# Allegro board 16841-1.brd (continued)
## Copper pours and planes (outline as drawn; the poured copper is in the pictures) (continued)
DCBATOUT on TOP: 184.81,2.63 184.55,2.88 184.55,5.68 179.98,10.25 179.98,16.72 178.84,17.87 175.28,17.87 171.41,21.74 171.41,28.6 167.28,32.73 167.28,38.44 167.41,38.57 167.41,51.27 167.66,51.52 168.42,51.52 168.68,51.78 168.68,52.28 168.42,52.54 167.28,52.54 167.28,54.95 169.82,54.95 170.58,54.19 171.22,54.19 172.49,52.92 172.49,51.27 172.55,51.21 172.55,50.57 172.11,50.13 172.11,46.44 174.77,43.78 178.46,43.78 181.5,46.82 181.5,47.97 182.01,48.47 185.31,48.47 185.57,48.22 185.57,44.66 185.31,44.41 180.49,44.41 178.46,42.38 178.46,33.11 180.74,30.82 185.57,30.82 186.33,31.58 186.33,32.47 186.58,32.73 190.14,32.73 191.28,31.58 191.28,26.5 190.39,25.61 176.55,25.61 175.15,24.22 175.15,21.8 176.42,20.53 184.17,20.53 187.47,17.23 187.47,10.12 188.49,9.1 188.49,2.88 188.23,2.63 ; 6 cut-outs
DCBATOUT on BOTTOM: 123.97,1.61 123.72,1.87 123.72,4.15 124.73,4.15 124.73,6.56 125.88,6.56 126,6.44 126,1.87 125.75,1.61
DCBATOUT on BOTTOM: 52.47,100.04 52.34,100.16 52.34,100.93 52.98,101.56 52.98,103.21 53.11,103.34 54.5,103.34 54.76,103.08 54.76,100.93 53.87,100.04
DCBATOUT on BOTTOM: 181.76,44.66 181.5,44.92 181.5,47.84 182.14,48.47 185.44,48.47 185.57,48.35 185.57,44.79 185.44,44.66
DCBATOUT on BOTTOM: 180.74,24.98 180.61,25.11 180.61,29.04 180.87,29.3 182.01,29.3 182.39,29.68 182.39,32.85 182.52,32.98 184.68,32.98 185.19,33.49 193.06,33.49 193.19,33.36 193.19,32.47 193.06,32.35 191.79,32.35 191.41,31.96 191.16,31.96 190.77,31.58 190.77,27.77 191.41,27.14 191.41,25.87 191.16,25.61 182.27,25.61 182.01,25.36 182.01,25.11 181.88,24.98 ; 3 cut-outs
DCBATOUT on BOTTOM: 140.74,106.01 140.63,106.11 140.63,111.39 140.43,111.59 138.83,111.59 138.58,111.85 138.58,114.13 138.7,114.26 143.78,114.26 144.17,113.88 144.17,106.13 144.04,106.01 ; 3 cut-outs
DCBATOUT on BOTTOM: 167.66,33.36 167.53,33.49 167.53,36.54 167.91,36.92 169.69,36.92 169.82,37.04 169.82,41.74 172.23,41.74 172.36,41.62 172.36,34.76 170.96,33.36
DCBATOUT on BOTTOM: 189.38,72.22 189.25,72.35 189.25,73.44 189.24,73.46 189.25,73.47 189.25,73.76 189.76,74.27 190.96,74.27 191.59,74.89 192.68,74.89 193.44,75.65 198.67,75.65 198.85,75.48 198.85,74.21 199.12,73.94 199.12,73.46 199.03,73.37 198.65,73.37 198.39,73.62 198.39,74.51 198.14,74.76 197,74.76 196.36,74.13 194.58,74.13 194.33,73.87 194.33,72.48 194.08,72.22 ; 3 cut-outs
DCBATOUT on BOTTOM: 169.82,47.59 169.82,51.4 169.69,51.52 168.8,51.52 168.68,51.65 168.68,52.16 168.3,52.54 167.28,52.54 167.28,55.84 167.41,55.97 168.93,55.97 169.31,55.59 169.31,54.44 169.82,53.94 169.82,51.78 170.07,51.52 170.07,51.14 170.58,50.63 171.85,50.63 172.11,50.38 172.11,47.97 171.85,47.71 171.6,47.71 171.47,47.59 ; 2 cut-outs
DCBATOUT on BOTTOM: 187.35,62.32 187.35,63.46 186.71,64.1 185.57,64.1 185.19,64.48 185.19,67.14 185.31,67.27 187.98,67.27 188.36,66.89 188.36,66 190.52,63.84 190.52,62.44 190.39,62.32
DCBATOUT on BOTTOM: 118.89,100.54 118.77,100.67 118.77,101.69 118.64,101.81 86.51,101.81 86,102.32 84.88,102.32 84.73,102.17 81.66,102.17 81.55,102.27 81.55,103.21 81.68,103.34 120.67,103.34 121.56,104.23 121.56,105.75 122.32,106.51 123.59,106.51 123.97,106.89 123.97,113.88 124.35,114.26 129.43,114.26 129.56,114.13 129.56,111.72 129.43,111.59 127.78,111.59 127.5,111.31 127.5,105.73 126.51,104.74 126.51,101.31 125.88,100.67 124.23,100.67 124.1,100.8 122.7,100.8 122.45,100.54 ; 3 cut-outs
DCBATOUT on L3: 185.31,4.91 188.36,4.91 188.62,4.66 188.62,1.61 188.23,1.23 144.57,1.23 144.22,1.59 144.22,2.58 144.77,3.14 154.2,3.14 154.96,3.9 175.03,3.9 175.53,3.39 183.79,3.39
DCBATOUT on L3: 121.31,102.96 121.31,103.21 121.05,103.47 120.16,103.47 120.04,103.34 82.19,103.34 81.94,103.08 81.94,99.96 83.13,98.77 87.8,98.77 88.39,99.35 89.35,99.35 89.38,99.33 117.67,99.33
DCBATOUT on L4: 81.94,102.7 82.19,102.45 115.72,102.45 116.35,101.81 121.05,101.81 121.81,102.58 121.81,103.08 121.56,103.34 82.06,103.34 81.94,103.21
DCBATOUT on L4: 175.28,4.28 175.79,3.77 184.55,3.77 185.06,4.28 188.49,4.28 188.74,4.02 188.74,1.61 188.36,1.23 126.39,1.23 126.32,1.29 126.26,1.23 124.23,1.23 123.85,1.61 123.85,5.68 123.86,5.69 123.86,6.91 126.08,9.13 132.79,9.13 135.94,5.98 139.8,5.98 140.28,5.5 141.4,5.5 142.44,4.46 161.79,4.46 162.45,3.8 162.45,3.01 162.71,2.75 163.34,2.75 163.47,2.88 163.47,4.02 163.49,4.05 163.49,4.51 163.77,4.79 171.9,4.79 172.41,4.28
DCBATOUT on L6: 124.23,105.62 123.97,105.88 123.97,113.88 124.23,114.13 127.53,114.13 129.43,116.04 142.01,116.04 144.17,113.88 144.17,106.13 144.04,106.01 140.61,106.01 140.48,106.13 140.48,112.61 139.97,113.12 129.81,113.12 127.66,110.96 127.66,105.88 127.4,105.62
DCBATOUT on L6: 53.61,103.34 84.48,103.34 84.6,103.21 84.6,101.31 83.84,100.54 54,100.54 53.36,101.18 53.36,103.08
DCBATOUT on L6: 182.96,59.21 182.96,62.25 183.66,62.95 183.66,68.48 184.61,69.43 184.61,71.4 187.09,73.87 191.41,73.87 192.55,75.02 195.6,75.02 195.85,74.76 195.85,73.11 190.01,67.27 190.01,62.57 189.25,61.81 189.25,60.16 187.73,58.63 187.73,55.59 187.79,55.52 187.79,50.44 185.69,48.35 185.69,44.41 184.55,43.27 180.36,43.27 178.2,41.11 178.2,33.49 179.98,31.71 183.54,31.71 184.68,30.57 188.11,30.57 189.63,29.04 191.03,29.04 191.41,28.66 191.41,27.77 191.03,27.39 173.88,27.39 167.91,33.36 167.91,44.28 167.98,44.35 167.98,55.4 170.07,57.49 170.07,61.17 168.55,62.7 168.55,68.16 169.31,68.92 169.31,69.56 168.93,69.94 166.01,69.94 165.12,70.83 164.74,70.83 164.49,71.08 164.49,72.22 164.61,72.35 172.11,72.35 175.53,68.92 175.53,63.97 174.14,62.57 174.14,59.02 176.04,57.11 180.87,57.11
DCBATOUT_CAMERA on TOP: 114.57,96.99 114.32,97.24 114.32,101.18 115.21,102.07 116.48,102.07 116.73,101.81 116.73,100.54 115.46,99.27 115.46,97.75 114.7,96.99 ; 4 cut-outs
DCBATOUT_CAMERA on BOTTOM: 114.22,96.02 114.19,96.05 114.19,98.03 114.4,98.23 115.21,98.23 115.29,98.16 115.29,96.15 115.16,96.02
DCBATOUT_LCD on TOP: 88.54,93.81 87.52,94.83 87.52,99.02 87.78,99.27 91.97,99.27 92.53,98.72 92.53,96.25 90.09,93.81 ; 3 cut-outs
DCBATOUT_LCD on BOTTOM: 90.11,95.96 89.93,96.14 89.93,96.84 89.92,96.84 89.92,97.72 89.91,97.73 89.91,97.98 90.11,98.18 92.04,98.18 92.58,97.65 92.58,97.22 92.43,97.07 92.07,97.07 92,97 92,96.01 91.95,95.96
EC_AGND on TOP: 146.71,2.25 146.58,2.37 146.58,4.41 146.83,4.66 149.37,4.66 149.5,4.53 149.5,3.77 149.75,3.52 150.26,3.52 150.26,2.37 150.13,2.25 148.74,2.25 148.67,2.31 148.61,2.25 ; 7 cut-outs
ECVBAT on TOP: 160.17,2.88 160.04,3.01 160.04,3.64 159.91,3.77 159.41,3.77 159.28,3.9 159.28,4.41 159.41,4.53 162.45,4.53 162.58,4.41 162.58,4.02 162.45,3.9 161.95,3.9 161.82,3.77 161.82,3.14 161.69,3.01 160.8,3.01 160.68,2.88 ; 1 cut-out
EDP_COMP on TOP: 125.88,63.08 125.75,63.21 125.75,64.48 126.39,65.11 128.04,65.11 128.16,64.98 128.16,64.1 128.04,63.97 126.77,63.97 126.51,63.71 126.51,63.21 126.39,63.08
EDRAM_OPIO_RCOMP on TOP: 126.24,71.79 126.16,71.86 126.16,72.34 125.93,72.57 125.5,72.57 125.4,72.67 125.4,73.13 125.47,73.21 125.93,73.21 126.29,72.85 126.64,72.85 126.77,72.98 127.02,72.98 127.1,72.9 127.1,72.6 126.69,72.19 126.69,71.91 126.57,71.79
FAN_VCC_1 on TOP: 202.59,68.54 202.33,68.79 202.33,69.05 203.98,70.7 203.98,74.26 204.36,74.64 206.27,74.64 206.52,74.38 206.52,72.22 206.4,72.1 205.63,72.1 205.13,71.59 205.13,70.7 202.97,68.54 ; 3 cut-outs
FBA_PLL_AVDD on L3: 162.33,90 168.04,90 168.17,89.88 168.17,85.56 168.8,84.92 168.8,84.42 168.68,84.29 167.91,84.29 167.66,84.54 167.66,88.73 167.15,89.24 163.47,89.24 162.07,87.84 156.99,87.84 156.48,88.35 150.9,88.35 150.52,88.73 150.52,89.24 150.64,89.37 157.63,89.37 158.39,88.61 161.31,88.61 162.2,89.5 162.2,89.88
GPU_PLL_VDD on L6: 163.98,76.54 163.98,76.03 162.96,75.02 162.96,70.57 163.6,69.94 165.12,69.94 165.25,70.06 165.25,70.32 164.99,70.57 164.61,70.57 164.23,70.95 164.23,74.51 164.99,75.27 164.99,76.16 164.49,76.67 164.1,76.67
GT_CORE on TOP: 123.21,59.4 122.83,59.78 122.83,62.44 122.96,62.57 122.96,63.46 123.08,63.59 124.35,63.59 124.99,64.22 125.37,64.22 125.62,63.97 125.62,63.46 125.37,63.21 124.99,63.21 124.73,62.95 124.73,62.7 125.12,62.32 125.37,62.32 125.62,62.06 125.62,60.41 125.37,60.16 124.73,60.16 124.61,60.03 124.61,59.65 124.35,59.4
GT_CORE on BOTTOM: 126,59.65 126,60.41 124.99,60.41 124.73,60.67 124.73,64.1 124.89,64.25 125.29,64.25 125.72,63.82 125.85,63.82 125.98,63.94 125.98,64.53 126.05,64.6 126.13,64.6 126.26,64.73 126.39,64.73 126.51,64.6 126.51,59.78 126.39,59.65
GT_CORE on L4: 131.21,65.49 130.07,65.49 129.18,64.6 129.18,62.83 128.8,62.44 126.39,62.44 126,62.83 126,63.97 125.5,64.48 124.86,64.48 124.48,64.1 124.48,59.96 124.63,59.8 125.14,59.8 125.47,59.47 125.47,59.02 125.72,58.76 128.04,58.76 129.56,60.29 129.56,60.41 130.45,61.3 131.34,61.3 131.47,61.43 131.47,62.7 130.96,63.21 130.96,64.6 131.34,64.98 131.34,65.37
GTX_CORE on TOP: 114.7,60.41 114.57,60.54 114.57,64.73 114.83,64.98 116.1,64.98 116.23,64.86 116.23,60.54 116.1,60.41
GTX_CORE on BOTTOM: 115.34,58.48 114.81,59.01 114.81,59.16 115.26,59.62 115.26,60.25 114.81,60.71 114.81,61.02 115.29,61.5 115.29,62.03 115.16,62.16 114.75,62.16 114.58,61.98 114.5,61.98 114.35,62.13 114.35,64.22 114.45,64.32 114.45,64.98 114.57,65.11 115.97,65.11 116.25,64.83 116.25,59.26 115.47,58.48
JGND on TOP: 17.55,89.5 17.04,90 17.04,91.02 16.02,92.04 15.9,92.04 15.9,92.92 15.39,93.43 15.39,96.73 15.64,96.99 18.56,96.99 18.69,96.86 18.69,94.7 19.32,94.07 19.32,89.88 18.94,89.5 ; 4 cut-outs
JGND on BOTTOM: 15.23,89.95 15.01,90.18 15.01,93.05 15.26,93.31 18.44,93.31 18.69,93.05 18.69,91.91 18.44,91.65 17.83,91.65 17.75,91.58 17.75,89.95
LCDVDD on BOTTOM: 100.73,91.91 100.48,92.16 100.48,93.69 100.73,93.94 102.13,93.94 103.02,94.83 103.09,94.83 103.63,95.36 104.39,95.36 104.72,95.69 104.72,96.89 104.77,96.94 106.47,96.94 106.5,96.91 106.5,92.47 105.94,91.91 ; 5 cut-outs
M_VREF_CA_DIMMA on TOP: 62.89,43.52 62.63,43.78 62.63,44.54 63.79,45.69 69.25,45.69 69.43,45.87 69.43,47.13 69.55,47.26 70.07,47.26 70.19,47.14 70.19,46 70.82,45.36 70.82,44.6 70.7,44.47 68.97,44.47 68.43,45.01 64.37,45.01 63.39,44.03 63.39,43.65 63.27,43.52
M_VREF_CA_DIMMB on TOP: 48.41,40.47 48.41,41.11 48.66,41.36 48.66,42.76 49.17,42.76 49.68,43.27 49.68,44.03 49.8,44.16 50.19,44.16 50.41,43.93 50.41,43.01 49.91,42.51 49.68,42.51 49.68,40.73 49.42,40.47 ; 1 cut-out
PS_ID on L3: 155.49,24.9 155.49,24.47 155.57,24.4 156.53,24.4 157.12,24.98 157.12,25.61 156.99,25.74 156.36,25.74 155.52,24.9
PWR_1D0V_PH on BOTTOM: 112.03,1.61 111.65,1.99 111.65,6.18 111.83,6.36 114.45,6.36 114.52,6.29 114.52,4.84 114.57,4.79 115.08,4.79 115.39,4.48 115.49,4.48 115.6,4.6 116.54,4.6 116.67,4.72 116.67,5.23 116.8,5.36 120.35,5.36 120.48,5.23 120.48,4.22 120.35,4.09 117.81,4.09 117.75,4.02 117.62,4.02 117.62,1.99 117.24,1.61
PWR_1D2V on BOTTOM: 18.31,61.81 18.18,61.94 18.18,63.33 18.05,63.46 16.53,63.46 16.4,63.59 16.4,66 16.78,66.38 20.72,66.38 20.85,66.25 20.85,64.98 20.72,64.86 19.58,64.86 19.45,64.73 19.07,64.73 18.94,64.6 18.94,61.94 18.82,61.81 ; 5 cut-outs
PWR_1D05V_FB on BOTTOM: 157.17,123.79 157.09,123.86 156.31,123.86 156.31,124.42 156.23,124.5 156.23,125.44 158.01,125.44 158.14,125.31 158.14,123.91 158.01,123.79 ; 2 cut-outs
PWR_1D05V_PHASE on BOTTOM: 152.04,121.88 151.53,122.39 149.88,122.39 149.75,122.52 149.75,124.55 150.01,124.8 151.4,124.8 151.66,124.55 151.66,123.79 152.29,123.15 154.07,123.15 154.12,123.1 154.12,121.93 154.07,121.88
PWR_1D05V_PVDD on BOTTOM: 159.53,120.74 158.9,121.37 156.61,121.37 156.31,121.68 156.31,122.69 157.2,122.69 157.25,122.64 159.91,122.64 160.42,123.15 160.42,125.31 160.68,125.56 161.69,125.56 161.82,125.44 161.82,123.28 161.69,123.15 161.69,120.86 161.56,120.74 ; 4 cut-outs
PWR_1D35V_LDO_P5 on BOTTOM: 191.61,80.81 190.27,82.16 190.27,83.58 190.34,83.65 191.03,83.65 191.16,83.53 191.16,83.1 191.97,82.28 191.97,80.81 ; 1 cut-out
PWR_1D35V_PGOOD on BOTTOM: 190.65,76.03 190.52,76.16 190.52,78.04 191.61,79.13 191.98,79.13 191.98,78.13 191.92,78.07 191.92,76.16 191.79,76.03 ; 1 cut-out
PWR_1D35V_PHASE on BOTTOM: 192.63,80.81 192.63,81.95 191.41,83.17 191.41,83.78 191.28,83.91 190.9,83.91 190.77,84.03 190.77,86.07 191.16,86.45 193.57,86.45 194.08,85.94 194.08,81.9 192.98,80.81 ; 2 cut-outs
PWR_2D5V on BOTTOM: 44.34,9.36 44.22,9.49 44.22,14.06 44.34,14.18 45.74,14.18 46.12,14.57 46.12,14.93 46.48,15.29 46.94,15.29 47.26,14.97 47.26,9.87 46.76,9.36 ; 6 cut-outs
PWR_3D3V on BOTTOM: 193.82,44 193.03,44.79 188.74,44.79 188.49,45.05 188.49,50.63 188.87,51.01 194.33,51.01 194.71,50.63 194.71,49.87 194.46,49.62 194.33,49.62 194.2,49.49 194.2,44.16 194.05,44 ; 2 cut-outs
PWR_3D3V_LDO on BOTTOM: 193.06,53.68 192.93,53.81 192.93,54.82 192.68,55.08 191.51,55.08 191.36,55.23 191.36,56.4 191.69,56.4 192.09,55.99 193.87,55.99 193.95,55.92 193.95,53.81 193.82,53.68 ; 1 cut-out
PWR_3D3V_PH on BOTTOM: 188.62,52.79 188.23,53.17 188.23,54.44 188.56,54.77 188.74,54.77 190.37,56.4 190.7,56.4 190.7,55.28 191.28,54.7 191.28,52.92 191.16,52.79
PWR_3V_PG on BOTTOM: 191.36,58.08 191.36,59.09 191.54,59.27 191.54,60.92 191.66,61.05 193.06,61.05 193.19,60.92 193.19,59.55 191.71,58.08 ; 1 cut-out
PWR_5V on TOP: 197.51,53.05 197.38,53.17 197.38,58.63 197.76,59.02 200.43,59.02 200.93,58.51 200.93,53.17 200.81,53.05
PWR_5V on BOTTOM: 201.32,51.65 200.93,52.03 197.63,52.03 197.38,52.28 197.38,61.68 197.76,62.06 201.32,62.06 201.57,61.81 201.57,52.92 201.95,52.54 201.95,51.78 201.82,51.65 ; 2 cut-outs
PWR_5V_LDO on BOTTOM: 197.51,67.78 197.38,67.91 197.38,69.07 197.2,69.25 197.2,69.43 198.01,69.43 198.14,69.3 198.65,69.3 198.78,69.43 198.78,69.81 199.03,70.06 199.54,70.06 199.54,69.18 199.66,69.05 199.92,69.05 200.17,68.79 200.17,67.91 200.05,67.78 ; 1 cut-out
PWR_5V_PG on BOTTOM: 196.44,71.03 196.44,72.05 196.45,72.06 196.45,72.8 196.74,73.09 198.67,73.09 198.69,73.07 198.79,73.07 198.88,72.99 198.88,72.53 198.42,72.07 197.38,72.07 197.15,71.84 197.15,71.39 196.79,71.03 ; 2 cut-outs
PWR_5V_PH on BOTTOM: 196.74,64.22 195.47,65.49 195.09,65.49 194.84,65.75 194.84,68.77 195.42,69.35 195.78,69.35 195.78,68.34 195.83,68.29 196.11,68.29 196.36,68.03 196.36,67.65 196.87,67.14 201.32,67.14 201.44,67.02 201.44,64.73 200.93,64.22 ; 1 cut-out
PWR_CHG_PHASE1 on BOTTOM: 179.88,37.15 178.96,38.06 174.77,38.06 173.88,38.95 173.88,43.9 174.07,44.09 178.39,44.09 179.34,43.14 181.76,43.14 181.88,43.01 181.88,40.98 182.27,40.6 183.51,40.6 183.61,40.5 183.61,37.15
PWR_CHG_PHASE2 on BOTTOM: 179.52,29.68 178.99,30.21 174.49,30.21 173.76,30.95 173.76,35.27 174.39,35.9 179.22,35.9 179.98,36.66 183.54,36.66 183.66,36.54 183.66,33.36 183.64,33.34 182.14,33.34 182.01,33.21 182.01,32.78 181.88,32.65 180.46,32.65 180.26,32.45 180.26,31.91 180.44,31.74 181.96,31.74 182.01,31.69 182.01,29.93 181.76,29.68
PWR_CHG_VBATIN on BOTTOM: 179.22,24.98 178.96,25.23 177.44,25.23 176.83,25.84 175.18,25.84 175.18,27.55 176.19,27.55 177.31,28.66 178.58,28.66 179.09,29.17 180.23,29.17 180.36,29.04 180.36,25.11 180.23,24.98
PWR_DCBATOUT_1D0V on BOTTOM: 120.8,4.53 120.67,4.66 120.67,5.29 120.42,5.55 116.86,5.55 116.73,5.68 116.73,6.95 116.86,7.07 119.78,7.07 120.04,7.33 120.04,8.34 120.16,8.47 120.67,8.47 120.8,8.34 125.62,8.34 125.88,8.09 125.88,7.2 125.5,6.82 124.48,6.82 124.48,4.53 ; 1 cut-out
PWR_DCBATOUT_1D35V on BOTTOM: 193.31,75.91 193.19,76.03 193.19,76.54 193.82,77.18 193.82,78.57 193.14,79.26 193.14,80.56 194.41,80.56 195.09,81.24 196.24,81.24 196.36,81.11 196.36,76.41 196.49,76.29 196.49,75.91 ; 1 cut-out
PWR_DCBATOUT_3D3V on BOTTOM: 187.6,55.59 187.47,55.71 187.47,61.3 187.35,61.43 187.35,62.06 190.37,62.06 190.52,61.91 190.52,60.92 190.27,60.67 189.89,60.67 189.76,60.54 189.76,58.36 190.19,57.92 190.19,56.65 189.17,56.65 189.12,56.6 189.12,56.09 188.62,55.59 ; 1 cut-out
PWR_DCBATOUT_5V on BOTTOM: 186.96,69.18 186.84,69.3 186.84,70.06 186.96,70.19 187.73,70.19 188.36,70.83 188.87,70.83 189.25,71.21 189.25,71.84 189.38,71.97 194.15,71.97 195.27,70.85 195.27,69.61 194.28,69.61 194.23,69.56 189.12,69.56 188.74,69.18 ; 2 cut-outs
PWR_DCBATOUT_VCCGTA on BOTTOM: 168.8,37.81 168.42,38.19 167.15,38.19 167.03,38.31 167.03,39.2 166.9,39.33 162.38,39.33 162.38,41.67 162.45,41.74 169.57,41.74 169.57,37.93 169.44,37.81
PWR_DCBATOUT_VCCGTB on BOTTOM: 166.9,47.46 166.77,47.59 162.38,47.59 162.38,49.85 162.53,50 168.42,50 168.68,50.25 168.68,51.4 168.8,51.52 169.57,51.52 169.57,47.71 169.31,47.46
PWR_DCBATOUT_VCCSA on BOTTOM: 160.29,31.96 160.17,32.09 160.17,35.65 160.42,35.9 166.9,35.9 167.28,35.52 167.28,32.35 166.9,31.96 ; 2 cut-outs
PWR_DCBATOUT_VCORE on TOP: 164.87,52.54 164.61,52.79 164.61,54.57 164.87,54.82 167.03,54.82 167.03,52.54
PWR_DCBATOUT_VCORE on BOTTOM: 157.25,52.54 156.48,53.3 156.48,54.44 156.2,54.72 155.85,54.72 155.85,55.41 158.06,55.41 158.64,54.82 167.03,54.82 167.03,52.79 166.77,52.54
PWR_DCBATOUT_VDDQ on BOTTOM: 43.76,101 43.76,103.16 43.94,103.34 52.6,103.34 52.73,103.21 52.73,101.56 52.47,101.31 47.14,101.31 47.09,101.36 45.36,101.36 45,101 ; 2 cut-outs
PWR_VCCGT_SWA on BOTTOM: 155.34,38.7 154.96,39.08 154.96,39.58 155.21,39.84 155.47,39.84 155.6,39.97 155.6,42.25 155.72,42.38 159.53,42.38 159.74,42.18 159.74,39.33 158.97,39.33 158.34,38.7
PWR_VCCGT_SWB on BOTTOM: 155.6,46.82 155.6,50.89 156.1,51.4 159.41,51.4 159.79,51.01 159.79,47.59 158.9,47.59 158.64,47.33 158.64,46.95 158.52,46.82
PWR_VCCSA_SW on BOTTOM: 156.99,28.15 155.85,29.3 155.85,33.74 156.48,34.38 158.01,34.38 158.11,34.28 159.63,34.28 159.66,34.25 159.66,31.96 159.91,31.71 161.44,31.71 161.56,31.58 161.56,28.41 161.31,28.15
PWR_VCORE_SW on BOTTOM: 155.85,58.05 155.85,59.27 155.34,59.78 155.34,64.22 155.47,64.35 158.14,64.35 158.26,64.22 158.26,59.22 158.06,59.02 158.06,58.05
PWR_VDDQ on BOTTOM: 35.07,93.69 35.07,102.07 35.2,102.2 37.61,102.2 37.87,101.94 37.87,99.4 39.01,98.26 39.52,98.26 39.64,98.13 39.64,93.69
PWR_VDDQ_PG on BOTTOM: 47.01,96.23 47.01,97.5 45.68,98.83 45.68,99.01 45.18,99.5 45.18,99.83 46.2,99.83 47.77,98.26 47.77,96.23
PWR_VDDQ_PH on BOTTOM: 39.26,99.53 38.88,99.91 38.88,101.94 39.14,102.2 42.16,102.2 43.5,100.85 43.5,100.49 42.13,100.49 41.17,99.53
PWR_VGA_CORE_PHASE1 on TOP: 127.27,100.8 126.77,101.31 126.77,104.61 127.91,105.75 127.91,111.21 128.04,111.34 130.83,111.34 130.96,111.21 130.96,105.37 132.1,104.23 132.1,102.83 133.62,102.83 133.88,102.58 133.88,101.05 133.62,100.8
PWR_VGA_CORE_PHASE1 on BOTTOM: 127.27,100.8 126.77,101.31 126.77,104.61 127.91,105.75 127.91,111.21 128.04,111.34 130.83,111.34 130.96,111.21 130.96,105.37 132.1,104.23 132.1,101.31 131.59,100.8
PWR_VGA_CORE_PHASE2 on TOP: 134.51,100.8 134.13,101.18 134.13,102.7 134.26,102.83 135.53,102.83 135.91,103.21 135.91,104.48 136.04,104.61 136.93,104.61 137.18,104.86 137.18,111.21 137.31,111.34 140.1,111.34 140.23,111.21 140.23,104.86 140.86,104.23 140.86,101.31 140.36,100.8
PWR_VGA_CORE_PHASE2 on BOTTOM: 135.53,100.8 135.28,101.05 135.28,104.48 135.4,104.61 136.93,104.61 137.18,104.86 137.18,111.21 137.31,111.34 140.1,111.34 140.23,111.21 140.23,104.86 140.86,104.23 140.86,101.31 140.36,100.8
RING2 on BOTTOM: 19.83,13.17 19.45,13.55 18.69,13.55 18.44,13.8 18.44,15.33 18.82,15.71 19.2,15.71 19.32,15.58 19.32,14.69 20.34,13.68 20.34,13.17
RING2 on L3: 19.45,15.84 19.45,15.2 19.2,14.95 18.82,14.95 17.55,16.22 16.4,16.22 16.28,16.34 16.28,17.11 16.4,17.23 18.05,17.23
RING2_R on BOTTOM: 17.73,11.01 17.66,11.08 17.66,11.31 17.66,11.31 18.44,12.09 18.44,13.17 18.56,13.3 19.45,13.3 19.58,13.17 19.58,11.14 19.45,11.01
SLEEVE on BOTTOM: 19.58,14.69 19.45,14.82 19.45,15.58 19.2,15.84 18.69,15.84 18.31,15.45 17.29,15.45 17.04,15.2 16.53,15.2 16.4,15.33 16.4,15.96 16.53,16.09 16.66,16.09 17.04,16.47 17.04,17.36 17.17,17.49 17.67,17.49 17.8,17.36 17.8,16.85 18.05,16.6 19.96,16.6 20.34,16.22 20.34,14.95 20.09,14.69
SLEEVE_R on BOTTOM: 17.04,11.39 16.78,11.64 16.78,12.03 17.29,12.53 17.29,15.2 18.31,15.2 18.31,12.15 17.55,11.39
SP_PLLVDD on TOP: 162.45,75.27 162.2,75.53 162.2,76.41 162.45,76.67 163.72,76.67 163.85,76.54 163.85,75.4 163.72,75.27 ; 1 cut-out
SP_PLLVDD on BOTTOM: 160.29,68.79 160.04,69.05 160.04,70.7 160.29,70.95 163.72,70.95 164.1,70.57 164.1,68.92 163.98,68.79 ; 3 cut-outs
SP_PLLVDD on L6: 162.07,76.92 163.6,76.92 163.72,76.8 163.72,76.16 162.33,74.76 162.33,70.32 162.07,70.06 160.8,70.06 160.42,70.45 160.42,75.27
TP_VDD on BOTTOM: 155.72,7.71 155.6,7.83 155.6,9.23 155.47,9.36 154.07,9.36 153.94,9.49 153.94,10.63 154.07,10.76 155.09,10.76 156.23,9.61 156.23,7.83 156.1,7.71
TP_VDD on BOTTOM: 123.21,13.17 122.96,13.42 122.96,15.71 123.08,15.84 124.48,15.84 124.61,15.96 124.61,16.47 124.99,16.85 124.99,17.74 125.12,17.87 125.88,17.87 126,17.74 126,16.72 126.39,16.34 127.02,16.34 127.15,16.22 127.15,15.45 126.89,15.2 125.12,15.2 124.99,15.07 124.99,13.55 124.61,13.17 ; 1 cut-out
TPAN_VDD on TOP: 79.52,97.62 79.27,97.88 79.27,99.4 79.65,99.78 80.79,99.78 80.92,99.66 80.92,97.88 80.67,97.62 ; 1 cut-out
TPAN_VDD on BOTTOM: 74.19,92.16 74.06,92.29 74.06,94.58 74.19,94.7 75.33,94.7 75.59,94.96 77.49,94.96 78.58,96.05 79.29,96.05 79.4,96.15 79.4,98.49 79.55,98.64 80.16,98.64 80.46,98.34 80.46,95.21 80.16,94.91 80.16,93.05 79.9,92.8 76.6,92.8 75.97,92.16
TYPEC_5V_SW on TOP: 34.56,86.07 34.18,86.45 34.18,89.24 34.31,89.37 35.33,89.37 35.45,89.5 35.45,91.4 35.58,91.53 36.93,91.53 37.05,91.4 37.05,91.17 36.72,90.84 36.72,88.48 36.6,88.35 35.58,88.35 35.45,88.23 35.45,86.32 35.2,86.07 ; 2 cut-outs
USB30_VCCA on BOTTOM: 20.72,44.03 20.59,44.16 20.59,44.79 20.72,44.92 20.98,44.92 21.23,45.17 21.23,48.73 20.98,48.98 20.09,48.98 19.45,49.62 18.18,49.62 18.18,50.28 18.23,50.33 19.27,50.33 19.58,50.63 19.58,51.14 19.32,51.4 13.99,51.4 13.74,51.65 13.74,53.05 13.99,53.3 22.12,53.3 23.13,52.28 23.13,44.41 22.75,44.03 ; 11 cut-outs
USB30_VCCB on TOP: 36.72,85.18 36.47,85.43 36.47,87.21 36.85,87.59 36.85,90.51 36.98,90.64 39.77,90.64 40.09,90.32 40.09,86.64 39.64,86.19 37.87,86.19 37.61,85.94 37.61,85.43 37.36,85.18
USB30_VCCB on BOTTOM: 14.12,32.98 13.48,33.62 13.48,37.68 14.75,38.95 14.75,39.33 14.88,39.46 15.39,39.46 15.51,39.33 15.51,38.06 15.77,37.81 17.8,37.81 17.9,37.71 18.79,37.71 18.79,36.64 18.44,36.28 15.9,36.28 15.64,36.03 15.64,34.5 15.77,34.38 17.83,34.38 17.93,34.28 18.79,34.28 18.79,33.08 18.69,32.98 ; 9 cut-outs
USB30_VCCB on BOTTOM: 25.04,35.27 24.66,35.65 24.66,43.27 28.47,47.08 28.47,50.25 32.66,54.44 32.66,64.22 31.26,65.62 31.26,66.38 30.75,66.89 29.99,66.89 28.21,68.67 28.21,70.83 27.58,71.46 27.58,77.05 28.21,77.68 28.21,83.4 31.9,87.08 38.12,87.08 38.25,86.96 38.25,84.03 37.74,83.53 34.06,83.53 33.04,82.51 33.04,70.57 35.33,68.29 35.45,68.29 36.34,67.4 36.34,65.24 37.23,64.35 37.23,59.52 36.34,58.63 36.34,52.67 32.02,48.35 32.02,45.3 27.58,40.85 27.58,35.65 27.2,35.27
USB30_VCCB on L4: 13.61,37.81 18.82,37.81 19.71,36.92 26.06,36.92 26.56,36.41 26.56,32.47 25.67,31.58 19.45,31.58 17.67,33.36 13.74,33.36 13.23,33.87 13.23,37.43
USB30_VCCC on TOP: 13.99,28.66 13.74,28.92 13.74,30.82 14.12,31.2 19.02,31.2 19.35,30.87 19.35,29.04 18.97,28.66 ; 3 cut-outs
USB30_VCCC on BOTTOM: 16.58,23.35 15.64,24.29 15.64,25.61 15.9,25.87 16.45,25.87 16.66,25.67 17.5,25.67 17.5,25.06 16.68,25.06 16.5,24.88 16.5,24.22 16.73,23.99 17.01,23.99 17.17,23.84 17.17,23.38 17.14,23.35
USB30_VCCC on BOTTOM: 13.86,27.9 13.61,28.15 13.61,29.81 13.67,29.87 13.67,30.5 14.12,30.95 17.8,30.95 18.18,30.57 18.21,30.57 18.31,30.47 19.17,30.47 19.17,29.17 18.92,28.92 16.53,28.92 15.51,27.9 ; 2 cut-outs
USB_ADT on TOP: 28.47,78.07 28.34,78.19 28.34,84.54 28.47,84.67 31.77,84.67 31.9,84.54 31.9,79.72 31.26,79.08 31.26,78.19 31.14,78.07 ; 2 cut-outs
USB_ADT_R1 on TOP: 31.64,78.32 31.39,78.57 31.39,78.95 32.02,79.59 32.02,81.62 32.28,81.88 33.29,81.88 33.55,81.62 33.55,78.57 33.29,78.32 ; 2 cut-outs
USB_TYPEC_DIS on TOP: 37.99,82.51 37.87,82.64 37.87,85.94 37.99,86.07 39.9,86.07 40.41,85.56 40.41,83.4 40.28,83.27 39.9,83.27 39.26,82.64 39.26,82.51
USBC1_CC1_CONN on TOP: 8.91,89.5 8.53,89.88 8.53,90.13 8.66,90.26 10.82,90.26 11.07,90 11.07,89.62 10.94,89.5
USBC1_CC2_CONN on TOP: 11.2,88.86 11.07,88.99 11.07,89.37 11.32,89.62 11.32,90 12.47,90 12.47,89.37 11.96,88.86 ; 1 cut-out
V_SM_VREF_CNTA on TOP: 70.51,46.7 70.38,46.82 70.38,47.97 70.89,47.97 71.01,47.84 71.01,47.71 71.39,47.33 73.68,47.33 74.44,48.09 74.95,48.09 75.08,47.97 75.08,47.71 74.06,46.7 ; 1 cut-out
V_SM_VREF_CNTB on TOP: 47.77,42.25 47.59,42.43 47.04,42.43 46.96,42.35 46.71,42.35 46.6,42.46 46.6,42.73 47.39,43.52 48.41,43.52 48.41,42.38 48.28,42.25 ; 1 cut-out
VGA_CORE on TOP: 152.55,82.64 145.94,89.24 142.64,89.24 141.12,90.77 138.32,90.77 137.69,91.4 136.29,91.4 135.15,92.54 128.04,92.54 127.53,93.05 127.53,97.88 128.8,99.15 140.23,99.15 145.37,94 147.78,94 150.39,91.4 151.15,91.4 155.16,87.39 166.19,87.39 166.46,87.13 166.46,86.52 166.89,86.09 166.89,85.98 166.71,85.81 157.09,85.81 156.96,85.68 156.96,84.89 157.21,84.64 166.31,84.64 166.87,84.08 166.87,83.85 166.62,83.61 156.74,83.61 156.72,83.63 155.98,83.63 154.98,82.64 ; 14 cut-outs
VGA_CORE on TOP: 160.55,78.57 160.42,78.7 160.42,80.04 160.55,80.17 164.99,80.17 165.06,80.09 165.06,78.82 164.99,78.74 164.91,78.74 164.74,78.57 ; 4 cut-outs
VGA_CORE on TOP: 157.26,81.39 157.19,81.46 157.19,82.12 157.29,82.22 166.79,82.22 166.92,82.1 166.92,81.54 166.76,81.39
VGA_CORE on BOTTOM: 136.16,87.59 134.77,88.99 127.68,88.99 127.17,89.5 127.17,98.67 127.78,99.27 139.47,99.27 139.97,98.77 139.97,96.48 139.47,95.97 139.47,92.67 139.72,92.42 141.88,92.42 142.51,91.78 142.51,88.99 141.12,87.59 ; 2 cut-outs
VGA_CORE on BOTTOM: outline of 83 points within 157.42,78.13 167.03,88.29
VGA_CORE on L2GND: 151.66,76.12 151.15,76.63 144.65,76.63 142.42,78.87 141.93,78.87 141.59,79.21 141.59,81.09 134.47,88.21 128.9,88.21 127.19,89.93 127.19,97.67 128.17,98.65 138.8,98.65 145.2,92.25 146.35,92.25 151.27,87.32 166.77,87.32 166.99,87.11 166.99,78.81 165.42,77.24 162.27,77.24 161.15,76.12
VGA_CORE on L3: 150.64,87.59 166.52,87.59 167.15,86.96 167.15,79.84 164.74,77.43 162.07,77.43 160.68,76.03 147.59,76.03 147.21,76.41 146.2,76.41 134.51,88.1 128.67,88.1 125.75,91.02 125.75,98.39 126,98.64 138.58,98.64 143.53,93.69 143.53,93.56 147.21,89.88 148.36,89.88
VGA_CORE on L6: 136.67,98.39 144.93,90.13 152.04,90.13 155.09,87.08 163.09,87.08 163.34,86.83 163.34,79.21 163.09,78.95 158.64,78.95 157.88,79.72 157.88,82.26 156.87,83.27 151.4,83.27 147.98,86.7 140.36,86.7 135.53,91.53 128.54,91.53 127.02,93.05 127.02,97.37 128.04,98.39
VREG3PD on TOP: 41.68,32.35 40.79,33.23 40.15,33.23 40.03,33.36 40.03,34 40.15,34.12 40.66,34.12 40.91,34.38 43.2,34.38 43.33,34.25 43.33,32.35 ; 3 cut-outs

Small or netless copper shapes (teardrops, artwork), in the pictures only: 1 on BOTTOM

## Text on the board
Ref Des/Silkscreen Bottom: X1802:32.768KHZ | F6501:.5A/6V | X2201:24MHZ | F5502:.5A/6V | X1801:24MHZ | X7601:27MHZ | NC | CLK | GND | IO | XRES | 3.3V | EDP2 | M2L2 | FAN | Only support DDR4 | DCIN | MADE IN TAIWAN | H7TJX | 16841-1 | Kylo Ren 15 | SPK | LED | KB | KBBL | EDP1 | TP | BYT | HDD | SSD | DIMM2 | DIMM1
Ref Des/Silkscreen Top: X5701:27MHZ | F5701:1.1A/6V | F5503:1.1A/24V | X2401:32.768KHZ
User.28: ByImpedance:100.0@_REF_L1=("3.0/9.0(L2)")|_REF_L6=("4.0/10.0(L5/L7)")|Type="DP"|_REF_L4=("4.0/6.5(L2/L5)")|_REF_L3=("4.0/6.5(L2/L5)" "4.0/10.0(L2/L4)")|imp="100.0"|_REF_L8=("3.0/9.0(L7)") | ByImpedance:33.0@_REF_L1=("8.0(L2)")|_REF_L6=("9.0(L5/L7)")|Type="SE"|_REF_L4=("11.0(L2/L5)")|_REF_L3=("11.0(L2/L5)" "9.0(L2/L4)")|imp="33.0"|_REF_L8=("8.0(L7)") | ByImpedance:35.0@_REF_L1=("7.5(L2)")|_REF_L6=("8.5(L5/L7)")|Type="SE"|_REF_L4=("10.0(L2/L5)")|_REF_L3=("8.5(L2/L4)" "10.0(L2/L5)")|imp="35.0"|_REF_L8=("7.5(L7)") | ByImpedance:37.5@_REF_L1=("6.5(L2)")|_REF_L6=("7.5(L5/L7)")|Type="SE"|_REF_L4=("9.0(L2/L5)")|_REF_L3=("9.0(L2/L5)" "7.5(L2/L4)")|imp="37.5"|_REF_L8=("6.5(L7)") | ByImpedance:40.0@_REF_L1=("6.0(L2)")|_REF_L6=("6.5(L5/L7)")|Type="SE"|_REF_L4=("8.0(L2/L5)")|_REF_L3=("8.0(L2/L5)" "6.5(L2/L4)")|imp="40.0"|_REF_L8=("6.0(L7)") | ByImpedance:42.0@_REF_L1=("5.0(L2)")|_REF_L6=("6.0(L5/L7)")|Type="SE"|_REF_L4=("7.0(L2/L5)")|_REF_L3=("7.0(L2/L5)" "6.0(L2/L4)")|imp="42.0"|_REF_L8=("5.0(L7)") | ByImpedance:45.0@_REF_L1=("4.5(L2)")|_REF_L6=("5.0(L5/L7)")|Type="SE"|_REF_L4=("6.5(L2/L5)")|_REF_L3=("6.5(L2/L5)" "5.0(L2/L4)")|imp="45.0"|_REF_L8=("4.5(L7)") | ByImpedance:50.0@_REF_L1=("3.5(L2)")|_REF_L6=("4.0(L5/L7)")|Type="SE"|_REF_L4=("5.0(L2/L5)")|_REF_L3=("5.0(L2/L5)" "4.0(L2/L4)")|imp="50.0"|_REF_L8=("3.5(L7)") | ByImpedance:55.0@Type="SE"|_REF_L4=("4.0(L2/L5)")|_REF_L3=("4.0(L2/L5)")|imp="55.0" | ByImpedance:60.0@_REF_L1=("7.5/4.0(L2)")|_REF_L6=("9.5/4.5(L5/L7)")|Type="DP"|_REF_L4=("10.5/4.5(L2/L5)")|_REF_L3=("9.5/4.5(L2/L4)" "10.5/4.5(L2/L5)")|imp="60.0"|_REF_L8=("7.5/4.0(L7)") | ByImpedance:63.0@_REF_L1=("7.0/4.5(L2)")|_REF_L6=("8.5/4.0(L5/L7)")|Type="DP"|_REF_L4=("9.5/4.0(L2/L5)")|_REF_L3=("9.5/4.0(L2/L5)" "8.5/4.0(L2/L4)")|imp="63.0"|_REF_L8=("7.0/4.5(L7)") | ByImpedance:70.0@_REF_L1=("6.0/5.0(L2)")|_REF_L6=("7.0/5.0(L5/L7)")|Type="DP"|_REF_L4=("8.5/5.0(L2/L5)")|_REF_L3=("8.5/5.0(L2/L5)" "7.0/5.0(L2/L4)")|imp="70.0"|_REF_L8=("6.0/5.0(L7)") | ByImpedance:72.0@_REF_L1=("5.5/4.5(L2)")|_REF_L6=("6.5/4.5(L5/L7)")|Type="DP"|_REF_L4=("7.5/5.0(L2/L5)")|_REF_L3=("7.5/5.0(L2/L5)" "6.5/4.5(L2/L4)")|imp="72.0"|_REF_L8=("5.5/4.5(L7)") | ByImpedance:75.0@_REF_L1=("5.0/4.5(L2)")|_REF_L6=("6.0/4.5(L5/L7)")|Type="DP"|_REF_L4=("7.0/5.0(L2/L5)")|_REF_L3=("7.0/5.0(L2/L5)" "6.0/4.5(L2/L4)")|imp="75.0"|_REF_L8=("5.0/4.5(L7)") | ByImpedance:80.0@_REF_L1=("4.5/5.0(L2)")|_REF_L6=("5.5/5.0(L5/L7)")|Type="DP"|_REF_L4=("6.0/5.0(L2/L5)")|_REF_L3=("6.0/5.0(L2/L5)" "5.5/5.0(L2/L4)")|imp="80.0"|_REF_L8=("4.5/5.0(L7)") | ByImpedance:83.0@_REF_L1=("3.5/4.0(L2)")|_REF_L6=("5.0/4.0(L5/L7)")|Type="DP"|_REF_L4=("5.5/4.5(L2/L5)")|_REF_L3=("5.5/4.5(L2/L5)" "5.0/4.0(L2/L4)")|imp="83.0"|_REF_L8=("3.5/4.0(L7)") | ByImpedance:85.0@_REF_L1=("4.0/5.0(L2)")|_REF_L6=("5.0/5.5(L5/L7)")|Type="DP"|_REF_L4=("5.5/5.0(L2/L5)")|_REF_L3=("5.0/5.5(L2/L4)" "5.5/5.0(L2/L5)")|imp="85.0"|_REF_L8=("4.0/5.0(L7)") | ByImpedance:88.0@_REF_L1=("4.0/7.0(L2)")|_REF_L6=("4.0/4.0(L5/L7)")|Type="DP"|_REF_L4=("5.0/5.0(L2/L5)")|_REF_L3=("4.0/4.0(L2/L4)" "5.0/5.0(L2/L5)")|imp="88.0"|_REF_L8=("4.0/7.0(L7)") | ByImpedance:90.0@_REF_L1=("4.0/8.0(L2)" "3.5/6.0(L2)")|_REF_L6=("4.0/4.5(L5/L7)")|Type="DP"|_REF_L4=("5.0/6.0(L2/L5)")|_REF_L3=("4.0/4.5(L2/L4)" "5.0/6.0(L2/L5)")|imp="90.0"|_REF_L8=("3.5/6.0(L7)" "4.0/8.0(L7)") | ByImpedance:95.0@_REF_L1=("3.5/10.0(L2)")|_REF_L6=("4.0/5.5(L5/L7)")|Type="DP"|_REF_L4=("4.0/4.5(L2/L5)")|_REF_L3=("4.0/4.5(L2/L5)" "4.0/5.5(L2/L4)")|imp="95.0"|_REF_L8=("3.5/10.0(L7)") | LayerIndex:nil | Source:8-1.0-16h.xls | artWorks:("_REF_L3" "_REF_L6" "_REF_L4" "_REF_L8" "_REF_L1") | gtImpOutlineUsed:BOARD GEOMETRY/PANEL_OUTLINE
User.29: Board Accuracy Check,Jun 21 09:11:34 2017,Passed | Dummy-Static-No Shape On Layer Check,Jun 21 09:11:35 2017,Passed | Split Plane Check,Jan 12 14:34:34 2017,Passed
User.38: AUD_AGND | GND
User.39: AUD_AGND | 5V_S0 | 3D3V_S0 | 3D3V_S5 | 5V_S5 | +VCCIO | +VCCPRIM_CORE | VGA_CORE | GND | VCC_CORE | +VCCGT
User.43: GND
User.45: Note:Refer to DRILL layer for ELLIPSE drill direction | FIGURE | SIZE | 10.0 | 16.0 | 22.0 | 28.0 | 40.0 | 115.0 | 178.0 | 30.0 | 44.0 | 63.0 | 71.0 | 86.0 | 119.0 | 158.0 | 40.0x20.0 | 44.0x20.0 | 60.0x24.0 | 60.0x36.0 | 63.0x24.0 | 67.0x36.0 | 90.0x28.0 | 138.0x98.0 | 138.0x118.0 | DRILL CHART: TOP to BOTTOM | ALL UNITS ARE IN MILS | PLATED | NON-PLATED | QTY | 4267 | 769 | 19 | 18 | 6 | 1 | 11 | 2 | 3 | 9 | 7 | 4 | This gerber is just for your reference to find the DP impedance traces in layer L1. | This gerber is just for your reference to find the DP impedance traces in layer L3. | This gerber is just for your reference to find the DP impedance traces in layer L4. | This gerber is just for your reference to find the DP impedance traces in layer L6. | This gerber is just for your reference to find the DP impedance traces in layer L8. | This gerber is just for your reference to find the SE impedance traces in layer L1. | This gerber is just for your reference to find the SE impedance traces in layer L3. | This gerber is just for your reference to find the SE impedance traces in layer L4. | This gerber is just for your reference to find the SE impedance traces in layer L6. | This gerber is just for your reference to find the SE impedance traces in layer L8. | DP IMPEDANCE TABLE: L1 | DP IMPEDANCE TABLE: L3 | DP IMPEDANCE TABLE: L4 | DP IMPEDANCE TABLE: L6 | DP IMPEDANCE TABLE: L8 | SE IMPEDANCE TABLE: L1 | SE IMPEDANCE TABLE: L3 | SE IMPEDANCE TABLE: L4 | SE IMPEDANCE TABLE: L6 | SE IMPEDANCE TABLE: L8 | * - Denotes that this Impedance | is NOT used | Model | Kylo Ren 15 | PCB_NO | 16841 | VER. | Layer | DRILL | L1 | L2GND | L3 | L4 | TMASK | TPLACE | TSILK | TSMD | Designer | AKIM | Date | 06/21/2017 | IMP(Ohm) | *33.0 | *60.0 | *35.0 | *63.0 | *37.5 | *70.0 | *40.0 | *72.0 | *42.0 | *75.0 | *45.0 | *80.0 | 45.0 | 80.0 | *83.0 | 50.0 | 83.0 | *55.0 | 85.0 | *88.0 | *90.0 | 90.0 | *95.0 | *100.0 | 100.0 | *50.0 | *85.0 | WIDTH(mils) | 8.0 | 9.0 | 7.5 | 8.5 | 6.5 | 6.0 | 5.0 | 4.5 | 3.5 | 4.0 | 11.0 | 7.0 | 7.5/4.0 | 7.0/4.5 | 6.0/5.0 | 5.5/4.5 | 5.0/4.5 | 4.5/5.0 | 3.5/4.0 | 4.0/5.0 | 4.0/7.0 | 3.5/6.0 | 4.0/8.0 | 3.5/10.0 | 3.0/9.0 | 10.5/4.5 | 9.5/4.5 | 8.5/4.0 | 9.5/4.0 | 7.0/5.0 | 8.5/5.0 | 6.5/4.5 | 7.5/5.0 | 6.0/4.5 | 5.5/5.0 | 5.0/4.0 | 5.0/5.5 | 4.0/4.0 | 5.0/5.0 | 4.0/4.5 | 5.0/6.0 | 4.0/5.5 | 4.0/10.0 | 4.0/6.5 | TYPE | SE | DP | Ref. Plane | L2 | L5/L7 | L7 | L2/L5 | L2/L4 | BMASK | BPLACE | BSILK | BSMD | L5VCC | L6 | L7GND | L8
